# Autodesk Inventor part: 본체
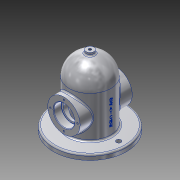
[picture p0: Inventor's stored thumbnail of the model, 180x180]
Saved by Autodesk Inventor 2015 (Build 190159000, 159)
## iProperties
Created: 2019-11
Part Number: 본체
Material: 알루미늄 6061
Document SubType Name: Modeling
Designer: 101020202
Density: 2.7 g/cm^3
Appearance: 알루미늄 - 평지
Mass: 1106.3 g
Surface Area: 883.188 cm^2
Volume: 409.741 cm^3
Author: 101020202
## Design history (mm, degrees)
sketch "스케치1"
  geometry: C1 r 70 at (0, 0); 1 further point
  constraints: 1 centre point, 1 coincident
  dimensions: "d0" = 140 diameter of C1
extrude "돌출1" new body sketch "스케치1" distance "d1" = 10; taper "d2" = 0 deg
sketch "스케치2"
  geometry: C1 r 70 at (0, 0) reference; C2 r 40 at (0, 0)
  constraints: 1 centre point, 1 coincident
  dimensions: "d3" = 80 diameter of C2
extrude "돌출2" join sketch "스케치2" distance "d4" = 120; taper "d5" = 0 deg
fillet "모깎기1" dims "d6" = 40
sketch "스케치3"
  geometry: L1 (-70, 0)-(-70, 10) reference; L2 (-70, 10)-(-40, 10) reference; L3 (-40, 10)-(-40, 90) reference; L4 (40, 90)-(40, 10) reference; L5 (40, 10)-(70, 10) reference; L6 (70, 10)-(70, 0) reference; L7 (70, 0)-(-70, 0) reference; C1 r 31 at (0, 50); A1 r 40 centre (0, 90) between (0, 130) and (-40, 90) reference; A2 r 40 centre (0, 90) between (40, 90) and (0, 130) reference; 2 further points
  constraints: 1 centre point, 1 midpoint, 1 vertical alignment
  dimensions: "d7" = 62 diameter of C1; "d8" = 50 distance of point (0, 0) C1.centre
extrude "돌출3" join sketch "스케치3" stored distance "d9" = 100; taper "d10" = 0 deg
sketch "스케치4"
  geometry: L1 (70, 10)-(70, 0) reference; L2 (70, 0)-(-70, 0) reference; L3 (-70, 0)-(-70, 10) reference; L4 (-70, 10)-(-40, 10) reference; L5 (-40, 10)-(-40, 19) reference; L6 (-40, 19)-(-50, 19) reference; L7 (-50, 19)-(-50, 81) reference; L8 (-50, 81)-(-40, 81) reference; L9 (-40, 81)-(-40, 90) reference; L10 (40, 90)-(40, 81) reference; L11 (40, 81)-(50, 81) reference; L12 (50, 81)-(50, 19) reference; L13 (50, 19)-(40, 19) reference; L14 (40, 19)-(40, 10) reference; L15 (40, 10)-(70, 10) reference; L16 (0, 0)-(30, 0); L17 (30, 0)-(30, 90); L18 (0, 120)-(0, 0); A1 r 40 centre (0, 90) between (40, 90) and (0, 130) reference; A2 r 40 centre (0, 90) between (0, 130) and (-40, 90) reference; A3 r 30 centre (0, 90) between (30, 90) and (0, 120)
  constraints: 6 end point, 2 point on circle, 1 centre point, 1 horizontal, 1 perpendicular, 1 vertical
  dimensions: "d11" = 30 radius of A3; "d12" = 10 distance between parallel lines of L10 L17; "d13" = 90 distance of L16.end L17.end; "d14" = 120 distance of L18.start L16.start
revolve "회전1" sketch "스케치4" stored, may be unused: angle "d15" = 90 deg
sketch "스케치5"
  geometry: C1 r 31 at (0, 0) reference; 1 further point
hole "구멍1" sketch "스케치5" at (0, 0) diameter "d16" = 33; stored, may be unused: countersink angle "d20" = 90 deg, drill point angle "d22" = 0 deg; dims "d17" = 6, "d18" = 40, "d19" = 15, "d21" = 40
sketch "스케치6"
  geometry: C1 r 20 at (0, 0) reference; 2 further points
  constraints: 1 vertical alignment
  dimensions: "d23" = 26 distance of C1.centre point (0, 26)
hole "구멍2" sketch "스케치6" at (0, 26) diameter "d24" = 3.242; stored, may be unused: countersink angle "d28" = 90 deg, drill point angle "d30" = 118 deg; dims "d25" = 8, "d26" = 40, "d27" = 15, "d29" = 10
node "작업 평면1"
sketch "스케치7"
  geometry: C1 r 7.5 at (0, 0); 1 further point
  constraints: 1 centre point, 1 coincident
  dimensions: "d35" = 15 diameter of C1
extrude "돌출4" join sketch "스케치7" stored distance "d36" = 100; taper "d37" = 0 deg
sketch "스케치8"
  geometry: C1 r 7.5 at (0, 0) reference
hole "구멍3" sketch "스케치8" at (0, 0) diameter "d38" = 5.188; stored, may be unused: countersink angle "d42" = 90 deg, drill point angle "d44" = 0 deg; dims "d39" = 12, "d40" = 40, "d41" = 15, "d43" = 20
sketch "스케치9"
  geometry: C1 r 40 at (0, 0) reference; C2 r 30 at (0, 0) reference; C3 r 40 at (0, 0) reference; C4 r 70 at (0, 0) reference; 2 further points
  constraints: 2 horizontal alignment
  dimensions: "d45" = 55 distance of C1.centre point (-55, 0); "d46" = 55 distance of C1.centre point (55, 0)
hole "구멍4" sketch "스케치9" at (-55, 0), (55, 0) diameter "d47" = 9; stored, may be unused: countersink angle "d51" = 90 deg, drill point angle "d53" = 0 deg; dims "d48" = 12, "d49" = 40, "d50" = 15, "d52" = 12
node "작업 평면2"
sketch "스케치10"
  geometry: L1 (-70, -10)-(70, -10) reference; 3 further points
  constraints: 1 midpoint, 1 vertical alignment, 1 other
  dimensions: "d54" = 50 distance from line of L1 point (0, 40)
feature "엠보싱1" sketch "스케치10" dims "d55" = 0.5, "d56" = 0
chamfer "모따기1" distance "d57" = 1; stored, may be unused: second distance "d58" = 2, angle "d59" = 45 deg
fillet "모깎기2" dims "d60" = 0.3
fillet "모깎기3" dims "d61" = 3
node "솔리드1"
mirror "대칭1"
pattern_circular "원형 패턴1" dims angle "d32" = 360 deg
mirror "대칭2"
node "절단 모서리 투영1"
node "절단 모서리 투영2"
node "절단 모서리 투영3"
other parameters: "d34" = 135
